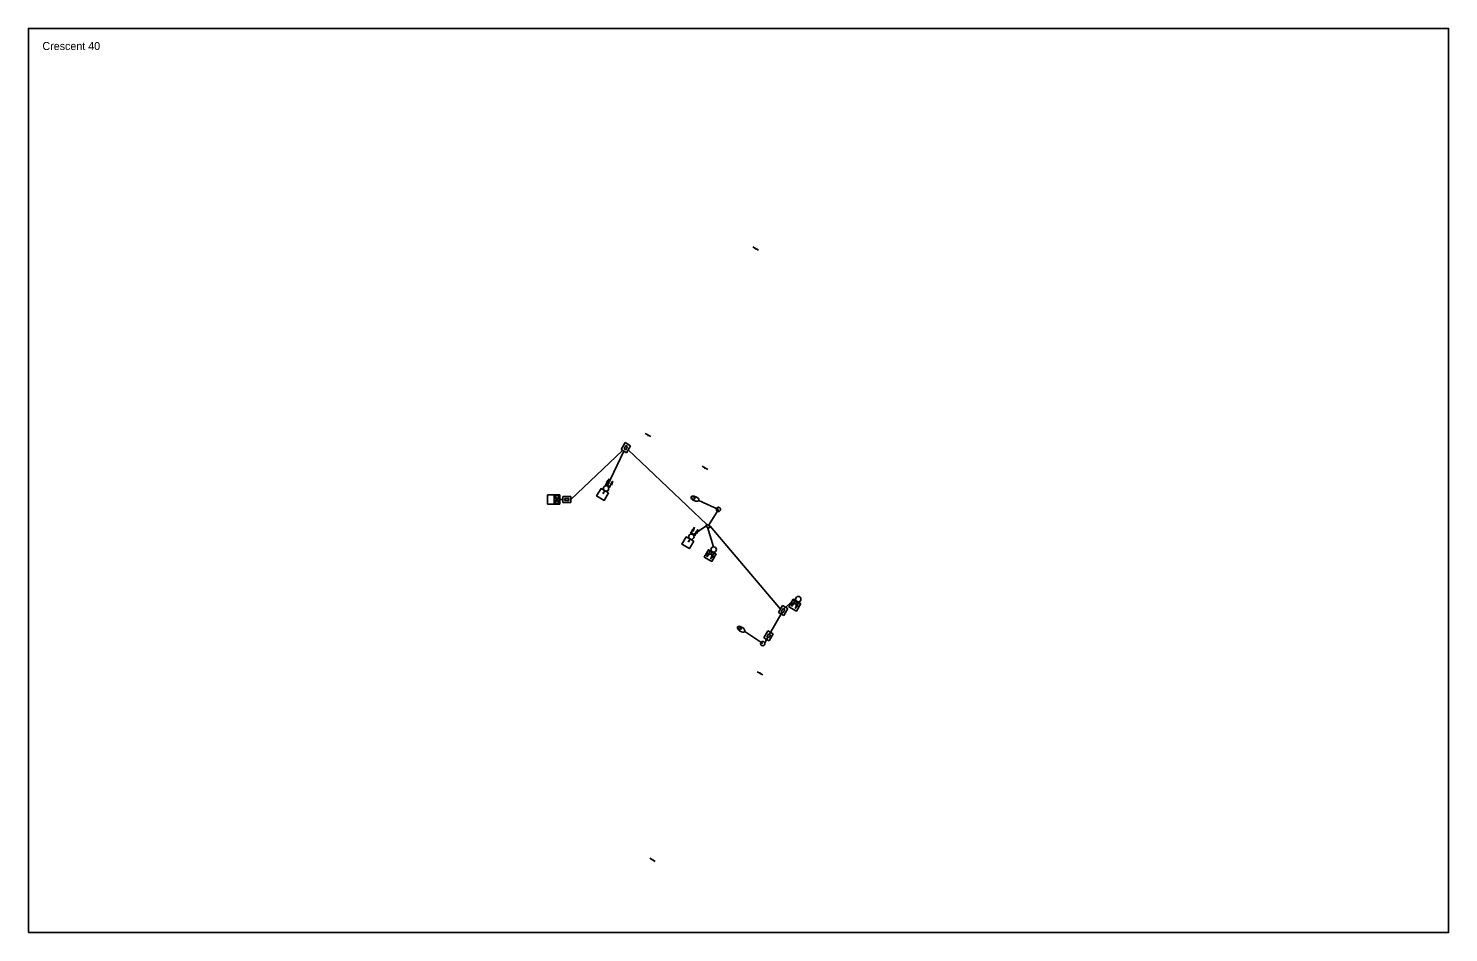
# Model space of a CAD drawing. Extents: x 995815 to 1000702, y 1981720 to 1984760.
# Drawn here: x 997773 to 998433, y 1983749 to 1984169 of the extents above; entities that cross this region are included whole.
import ezdxf

# ---------------------------------------------------------------- set-up
doc = ezdxf.new("R2010")
doc.units = 0
for name, color, linetype in [('DSN_Drain_Alignment_ArDOT_BMCD_Rt', 7, 'Continuous'), ('DSN_DRAIN_Analytics_ArDOT_BMCD_Rt', 7, 'Continuous'), ('DSN_DRFT_Common-Annotations', 7, 'Continuous'), ('DSN_DRFT_Const-No-Plot', 7, 'Continuous'), ('DSN_DRFT_Guideline-No-Plot', 7, 'Continuous'), ('DSN_DRFT_Junk-No-Plot', 7, 'Continuous'), ('DSN_RDWY_Alignment', 7, 'Continuous'), ('DSN_ROW_Point-Name-Annotation', 7, 'Continuous')]:
    doc.layers.add(name, color=color, linetype=linetype)

msp = doc.modelspace()

# ---------------------------------------------------------------- linework, layer by layer
at = {"layer": 'DSN_Drain_Alignment_ArDOT_BMCD_Rt'}
for centre in [(998093.82, 1983945.33), (998114.39, 1983883.01)]:
    msp.add_circle(centre, 1, dxfattribs=at)
at = {"layer": 'DSN_DRAIN_Analytics_ArDOT_BMCD_Rt'}
for points in [[(998042.7, 1983952.97), (998040.66, 1983949.53), (998037.22, 1983951.56), (998039.26, 1983955.01)], [(998082.34, 1983930.53), (998080.3, 1983927.09), (998076.86, 1983929.13), (998078.89, 1983932.57)], [(998092.7, 1983924.62), (998090.71, 1983921.15), (998087.24, 1983923.14), (998089.23, 1983926.61)], [(998132.03, 1983901.57), (998130.04, 1983898.1), (998126.57, 1983900.09), (998128.56, 1983903.56)]]:
    msp.add_lwpolyline(points, close=True, dxfattribs=at)
at = {"layer": 'DSN_DRFT_Common-Annotations'}
for p, q in [((998050.46, 1983976.35), (998048.58, 1983973.1)), ((998049.94, 1983973.47), (998050.82, 1983974.98)), ((998050.82, 1983974.98), (998049.94, 1983973.47)), ((998052.99, 1983974.88), (998050.46, 1983976.35)), ((998050.74, 1983973), (998051.62, 1983974.52)), ((998050.74, 1983973), (998051.62, 1983974.52)), ((998051.62, 1983974.52), (998050.82, 1983974.98)), ((998051.62, 1983974.52), (998050.82, 1983974.98)), ((998051.1, 1983971.64), (998052.99, 1983974.88)), ((998048.58, 1983973.1), (998051.1, 1983971.64)), ((998050.74, 1983973), (998049.94, 1983973.47)), ((998049.94, 1983973.47), (998050.74, 1983973)), ((998025.22, 1983951.38), (998021.47, 1983951.38)), ((998021.47, 1983951.38), (998021.47, 1983948.46)), ((998021.47, 1983948.46), (998025.22, 1983948.46)), ((998022.47, 1983949.46), (998022.47, 1983950.38)), ((998022.47, 1983950.38), (998024.22, 1983950.38)), ((998022.47, 1983950.38), (998022.47, 1983949.46)), ((998024.22, 1983950.38), (998022.47, 1983950.38)), ((998022.47, 1983949.46), (998024.22, 1983949.46)), ((998022.47, 1983949.46), (998024.22, 1983949.46)), ((998024.22, 1983949.46), (998024.22, 1983950.38)), ((998024.22, 1983949.46), (998024.22, 1983950.38)), ((998025.22, 1983948.46), (998025.22, 1983951.38)), ((998039.93, 1983953.08), (998040.68, 1983952.63)), ((998040.98, 1983953.99), (998040.31, 1983952.85)), ((998088.44, 1983938.35), (998087.97, 1983937.55)), ((998087.97, 1983937.55), (998089.49, 1983936.67)), ((998089.95, 1983937.47), (998088.44, 1983938.35)), ((998089.49, 1983936.67), (998089.95, 1983937.47)), ((998079.57, 1983930.64), (998080.32, 1983930.19)), ((998080.61, 1983931.55), (998079.94, 1983930.42)), ((998089.93, 1983924.69), (998090.69, 1983924.26)), ((998090.96, 1983925.62), (998090.31, 1983924.47)), ((998129.26, 1983901.64), (998130.02, 1983901.2)), ((998130.3, 1983902.56), (998129.64, 1983901.42)), ((998123.53, 1983900.68), (998121.66, 1983897.43)), ((998121.66, 1983897.43), (998124.2, 1983895.97)), ((998123.03, 1983897.8), (998123.9, 1983899.31)), ((998123.9, 1983899.31), (998123.03, 1983897.8)), ((998123.83, 1983897.34), (998123.03, 1983897.8)), ((998123.03, 1983897.8), (998123.83, 1983897.34)), ((998126.07, 1983899.22), (998123.53, 1983900.68)), ((998123.83, 1983897.34), (998124.7, 1983898.86)), ((998123.83, 1983897.34), (998124.7, 1983898.86)), ((998124.7, 1983898.86), (998123.9, 1983899.31)), ((998124.7, 1983898.86), (998123.9, 1983899.31)), ((998124.2, 1983895.97), (998126.07, 1983899.22)), ((998116.77, 1983888.93), (998114.9, 1983885.68)), ((998119.3, 1983887.47), (998116.77, 1983888.93)), ((998114.9, 1983885.68), (998117.43, 1983884.22)), ((998116.27, 1983886.04), (998117.14, 1983887.56)), ((998117.14, 1983887.56), (998116.27, 1983886.04)), ((998117.06, 1983885.59), (998116.27, 1983886.04)), ((998116.27, 1983886.04), (998117.06, 1983885.59)), ((998117.06, 1983885.59), (998117.94, 1983887.1)), ((998117.06, 1983885.59), (998117.94, 1983887.1)), ((998117.94, 1983887.1), (998117.14, 1983887.56)), ((998117.94, 1983887.1), (998117.14, 1983887.56)), ((998117.43, 1983884.22), (998119.3, 1983887.47))]:
    msp.add_line(p, q, dxfattribs=at)
at = {"layer": 'DSN_DRFT_Const-No-Plot'}
for p, q in [((998014.44, 1983952.04), (998020.18, 1983952.04)), ((998014.44, 1983952.04), (998014.44, 1983947.71)), ((998017.44, 1983952.04), (998017.44, 1983947.71)), ((998017.77, 1983951.71), (998017.77, 1983948.04)), ((998019.85, 1983948.04), (998017.77, 1983951.71)), ((998017.77, 1983951.71), (998019.85, 1983951.71)), ((998019.85, 1983951.69), (998017.77, 1983948.04)), ((998017.77, 1983948.04), (998019.85, 1983948.04)), ((998019.85, 1983951.71), (998019.85, 1983948.04)), ((998020.18, 1983952.04), (998020.18, 1983947.71)), ((998014.44, 1983947.71), (998020.18, 1983947.71))]:
    msp.add_line(p, q, dxfattribs=at)
at = {"layer": 'DSN_DRFT_Guideline-No-Plot'}
for p, q in [((998093.82, 1983945.33), (998084.72, 1983949.48)), ((998114.39, 1983883.01), (998106.05, 1983888.53))]:
    msp.add_line(p, q, dxfattribs=at)
for centre, major_axis in [((998082.9, 1983950.31), (-1.82, 0.83)), ((998081.99, 1983950.72), (0.91, -0.415)), ((998104.38, 1983889.64), (-1.67, 1.1)), ((998103.55, 1983890.19), (0.834, -0.552))]:
    msp.add_ellipse(centre, major_axis=major_axis, ratio=0.5, dxfattribs=at)
at = {"layer": 'DSN_DRFT_Junk-No-Plot'}
msp.add_line((998093.82, 1983945.33), (998093.47, 1983944.39), dxfattribs=at)
msp.add_lwpolyline([(997773.14, 1983748.75), (998433.14, 1983748.75), (998433.14, 1984168.75), (997773.14, 1984168.75)], close=True, dxfattribs=at)
at = {"layer": 'DSN_RDWY_Alignment'}
for p, q in [((998025.22, 1983949.92), (998049.19, 1983972.75)), ((998042.16, 1983956.19), (998049.91, 1983972.33)), ((998051.92, 1983973.04), (998088.44, 1983938.35)), ((998020.18, 1983949.87), (998021.47, 1983949.92)), ((998089.19, 1983937.91), (998093.82, 1983945.33)), ((998087.97, 1983937.55), (998082.12, 1983933.52)), ((998088.73, 1983937.11), (998091.55, 1983927.95)), ((998089.95, 1983937.47), (998122.6, 1983899.05)), ((998124.21, 1983899.14), (998129.73, 1983904.03)), ((998123.43, 1983897.57), (998117.54, 1983887.33)), ((998116.67, 1983885.81), (998115.37, 1983883.21))]:
    msp.add_line(p, q, dxfattribs=at)
at = {"layer": 'DSN_ROW_Point-Name-Annotation'}
for p, q in [((998112.36, 1984065.75), (998109.76, 1984067.24)), ((998110.83, 1984066.34), (998110.95, 1984066.56)), ((998110.83, 1984066.34), (998111.04, 1984066.22)), ((998111.17, 1984066.43), (998110.95, 1984066.56)), ((998111.17, 1984066.43), (998111.04, 1984066.22)), ((998062.42, 1983979.11), (998059.82, 1983980.6)), ((998060.89, 1983979.7), (998061.02, 1983979.92)), ((998060.89, 1983979.7), (998061.11, 1983979.58)), ((998061.23, 1983979.79), (998061.02, 1983979.92)), ((998061.23, 1983979.79), (998061.11, 1983979.58)), ((998088.9, 1983963.87), (998086.3, 1983965.37)), ((998087.37, 1983964.47), (998087.49, 1983964.69)), ((998087.37, 1983964.47), (998087.58, 1983964.34)), ((998087.71, 1983964.56), (998087.49, 1983964.69)), ((998087.71, 1983964.56), (998087.58, 1983964.34)), ((998043.68, 1983955.58), (998041.1, 1983957.11)), ((998041.53, 1983956.86), (998043.07, 1983959.46)), ((998042.26, 1983956.13), (998042.39, 1983956.35)), ((998043.25, 1983955.84), (998044.79, 1983958.44)), ((998083.31, 1983933.15), (998080.73, 1983934.68)), ((998081.17, 1983934.42), (998082.7, 1983937.02)), ((998082.89, 1983933.4), (998084.43, 1983936)), ((998081.9, 1983933.7), (998082.02, 1983933.91)), ((998089.97, 1983925.9), (998088.47, 1983923.28)), ((998089.54, 1983926.15), (998092.14, 1983924.65)), ((998091.7, 1983924.9), (998090.2, 1983922.28)), ((998090.96, 1983925.62), (998090.84, 1983925.4)), ((998129.3, 1983902.85), (998127.8, 1983900.23)), ((998128.87, 1983903.09), (998131.47, 1983901.6)), ((998131.03, 1983901.85), (998129.53, 1983899.23)), ((998130.3, 1983902.56), (998130.17, 1983902.35)), ((998111.8, 1983869.94), (998114.4, 1983868.44)), ((998112.99, 1983869.25), (998113.12, 1983869.47)), ((998112.99, 1983869.25), (998113.21, 1983869.13)), ((998113.34, 1983869.34), (998113.12, 1983869.47)), ((998113.34, 1983869.34), (998113.21, 1983869.13)), ((998061.87, 1983783.3), (998064.47, 1983781.8)), ((998063.06, 1983782.61), (998063.18, 1983782.83)), ((998063.4, 1983782.7), (998063.18, 1983782.83)), ((998063.06, 1983782.61), (998063.27, 1983782.49)), ((998063.4, 1983782.7), (998063.27, 1983782.49))]:
    msp.add_line(p, q, dxfattribs=at)
for centre in [(998041.62, 1983955.06), (998081.25, 1983932.62), (998091.59, 1983926.7), (998130.92, 1983903.65)]:
    msp.add_circle(centre, 1.25, dxfattribs=at)
for centre, radius, start, end in [((998031.65, 1983968.78), 14.74, 313.02995, 320.76806), ((998041.73, 1983957.19), 0.814, 27.52906, 91.2237), ((998056.73, 1983953.93), 14.74, 157.9847, 165.72281), ((998033.37, 1983967.76), 14.74, 313.02995, 320.76806), ((998043.45, 1983956.17), 0.814, 27.52906, 91.2237), ((998058.45, 1983952.91), 14.74, 157.9847, 165.72281), ((998071.29, 1983946.34), 14.74, 313.02995, 320.76806), ((998081.36, 1983934.75), 0.814, 27.52906, 91.2237), ((998096.37, 1983931.5), 14.74, 157.9847, 165.72281), ((998073.01, 1983945.32), 14.74, 313.02995, 320.76806), ((998098.09, 1983930.48), 14.74, 157.9847, 165.72281), ((998083.08, 1983933.73), 0.814, 27.52906, 91.2237), ((998074.73, 1983928.61), 14.74, 338.78393, 346.52204), ((998100.01, 1983914.12), 14.74, 133.82918, 141.56729), ((998089.78, 1983925.56), 0.814, 208.32829, 272.02293), ((998076.46, 1983927.62), 14.74, 338.78393, 346.52204), ((998101.75, 1983913.12), 14.74, 133.82918, 141.56729), ((998091.51, 1983924.57), 0.814, 208.32829, 272.02293), ((998114.06, 1983905.56), 14.74, 338.78393, 346.52204), ((998139.34, 1983891.07), 14.74, 133.82918, 141.56729), ((998129.11, 1983902.51), 0.814, 208.32829, 272.02293), ((998115.8, 1983904.56), 14.74, 338.78393, 346.52204), ((998141.08, 1983890.07), 14.74, 133.82918, 141.56729), ((998130.84, 1983901.52), 0.814, 208.32829, 272.02293)]:
    msp.add_arc(centre, radius, start, end, dxfattribs=at)

# ---------------------------------------------------------------- texts
at = {"layer": 'DSN_DRFT_Junk-No-Plot'}
msp.add_text('Crescent 40', height=3.72, rotation=359.97484, dxfattribs=at).set_placement((997779.65, 1984158.71))

doc.saveas('drawing.dxf')
